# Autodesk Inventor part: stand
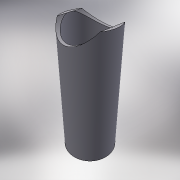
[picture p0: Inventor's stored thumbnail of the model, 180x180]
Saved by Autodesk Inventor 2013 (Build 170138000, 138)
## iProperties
Created: 2005-12
Part Number: stand
Material: Stainless Steel, 440C
Document SubType Name: Modeling
Designer: =<Author>
Manufacturer: Standard
Standards Organization: Custom
Density: 7.75 g/cm^3
Description: stand
Mass: 13.9115 g
Surface Area: 36.9303 cm^2
Volume: 1.79503 cm^3
Author: PVitaliy
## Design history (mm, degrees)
sketch "Эскиз2"
  geometry: C1 r 8 at (0, 0); C2 r 7 at (0, 0)
  constraints: 2 centre point, 1 other
  dimensions: "d0" = 16 diameter of C1; "d1" = 1 radial gap between concentric circles of C2 C1
extrude "Выдавливание1" new body sketch "Эскиз2" distance "d2" = 40; taper "d3" = 0 deg
sketch "Эскиз3"
  geometry: L1 (-8, 40)-(8, 40) reference; L2 (-8, 0)-(8, 0) reference; L3 (0, -10.4)-(0, 62.4) reference; C1 r 8 at (0, 44)
  constraints: 1 centre point, 1 point on line
  dimensions: "d4" = 16 diameter of C1; "d5" = 4 distance centre to line of C1 L1
extrude "Выдавливание2" cut sketch "Эскиз3" stored distance "d7" = 50; taper "d8" = 0 deg
body "Solid1"
